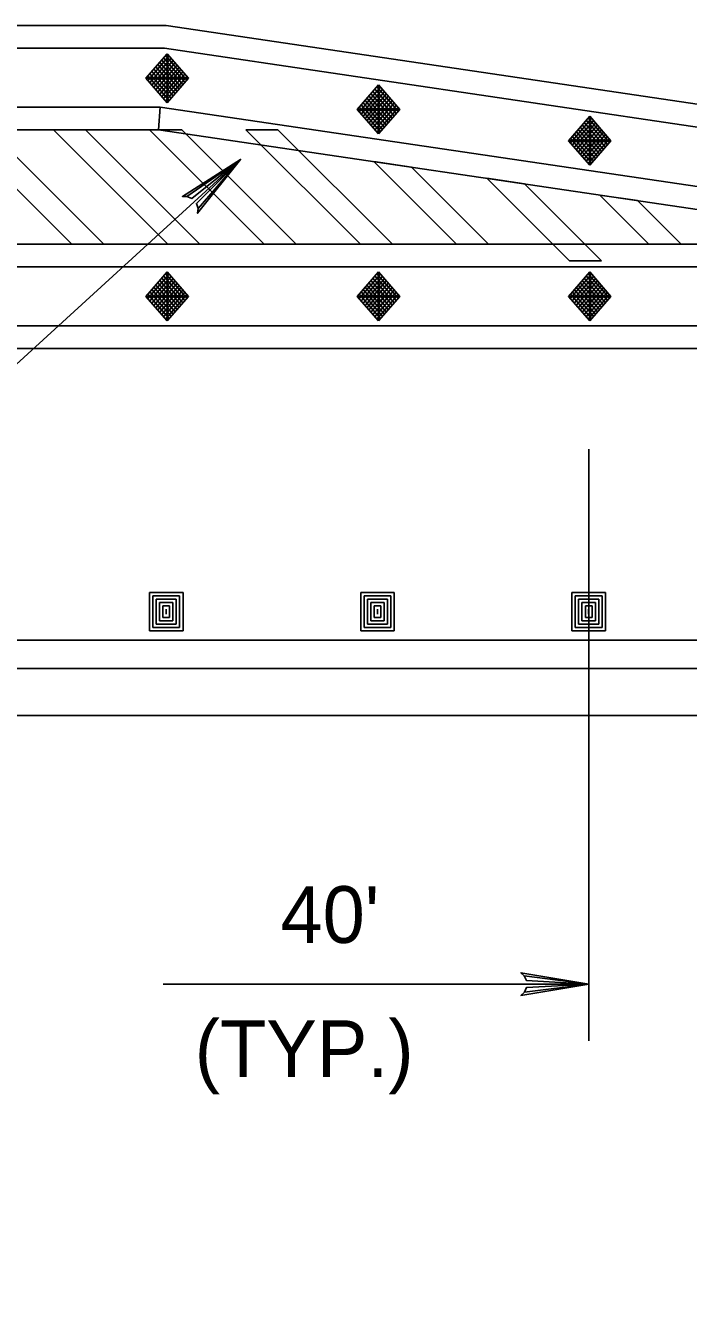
# Model space of a CAD drawing. Extents: x 639362 to 641108, y 298458 to 299646.
# Drawn here: x 639712.3 to 639747.4, y 298704.6 to 298772.2 of the extents above; entities that cross this region are included whole.
import ezdxf

# ---------------------------------------------------------------- set-up
doc = ezdxf.new("R2010")
doc.units = 0
doc.layers.add('2', color=7, linetype='Continuous')
doc.layers.add('3', color=7, linetype='Continuous')

# ---------------------------------------------------------------- blocks, each defined once
blk = doc.blocks.new('RARROW')
at = {"layer": '3'}
blk.add_lwpolyline([(-2.2695, 0.285), (-2.184875, 0.12075), (0, 0), (-2.2695, 0.285), (-2.38575, 0.384625), (0, 0), (-2.183125, -0.108), (-2.262875, -0.2705), (0, 0), (-2.38575, -0.379125), (-2.262875, -0.2705)], dxfattribs=at)

msp = doc.modelspace()

# ---------------------------------------------------------------- linework, layer by layer
at = {"layer": '2'}
for p, q in [((639719.726, 298772.157), (639431.255, 298772.157)), ((639797.996, 298760.59), (639719.726, 298772.157)), ((639431.255, 298770.957), (639719.637, 298770.957)), ((639719.779, 298770.666), (639718.652, 298769.371)), ((639719.884, 298770.547), (639718.77, 298769.268)), ((639719.637, 298770.957), (639797.908, 298759.39)), ((639719.696, 298770.57), (639720.823, 298769.275)), ((639720.907, 298769.371), (639719.779, 298770.666)), ((639719.779, 298770.666), (639719.779, 298768.076)), ((639719.988, 298770.427), (639718.86, 298769.131)), ((639720.092, 298770.307), (639718.965, 298769.011)), ((639720.197, 298770.187), (639719.069, 298768.891)), ((639719.069, 298769.851), (639720.197, 298768.555)), ((639720.301, 298770.067), (639719.174, 298768.771)), ((639719.174, 298769.971), (639720.301, 298768.675)), ((639719.278, 298770.091), (639720.406, 298768.795)), ((639720.406, 298769.947), (639719.278, 298768.651)), ((639719.382, 298770.211), (639720.51, 298768.915)), ((639720.51, 298769.827), (639719.382, 298768.531)), ((639719.487, 298770.331), (639720.614, 298769.035)), ((639719.591, 298770.451), (639720.719, 298769.155)), ((639718.652, 298769.371), (639719.779, 298768.076)), ((639718.652, 298769.371), (639720.907, 298769.371)), ((639718.756, 298769.491), (639719.884, 298768.196)), ((639718.86, 298769.611), (639719.988, 298768.315)), ((639718.965, 298769.731), (639720.092, 298768.435)), ((639720.614, 298769.707), (639719.487, 298768.411)), ((639720.719, 298769.587), (639719.591, 298768.292)), ((639720.823, 298769.467), (639719.696, 298768.172)), ((639719.779, 298768.076), (639720.907, 298769.371)), ((639730.963, 298769.014), (639729.835, 298767.718)), ((639731.067, 298768.894), (639729.954, 298767.615)), ((639731.172, 298768.774), (639730.044, 298767.478)), ((639731.276, 298768.654), (639730.149, 298767.359)), ((639731.381, 298768.534), (639730.253, 298767.239)), ((639730.462, 298768.438), (639731.589, 298767.143)), ((639730.566, 298768.558), (639731.694, 298767.263)), ((639730.671, 298768.678), (639731.798, 298767.383)), ((639730.775, 298768.798), (639731.903, 298767.502)), ((639730.879, 298768.918), (639732.007, 298767.622)), ((639732.091, 298767.718), (639730.963, 298769.014)), ((639730.963, 298769.014), (639730.963, 298766.423)), ((639719.409, 298767.845), (639606.893, 298767.845)), ((639719.409, 298767.845), (639719.32, 298766.645)), ((639719.32, 298766.645), (639719.409, 298767.845)), ((639776.623, 298759.39), (639719.409, 298767.845)), ((639729.94, 298767.838), (639731.067, 298766.543)), ((639730.044, 298767.958), (639731.172, 298766.663)), ((639730.149, 298768.078), (639731.276, 298766.783)), ((639730.253, 298768.198), (639731.381, 298766.903)), ((639731.485, 298768.414), (639730.357, 298767.119)), ((639730.357, 298768.318), (639731.485, 298767.023)), ((639731.589, 298768.294), (639730.462, 298766.999)), ((639731.694, 298768.174), (639730.566, 298766.879)), ((639731.798, 298768.054), (639730.671, 298766.759)), ((639731.903, 298767.934), (639730.775, 298766.639)), ((639732.007, 298767.814), (639730.879, 298766.519)), ((639729.835, 298767.718), (639730.963, 298766.423)), ((639729.835, 298767.718), (639732.091, 298767.718)), ((639730.963, 298766.423), (639732.091, 298767.718)), ((639742.147, 298767.361), (639741.019, 298766.066)), ((639742.251, 298767.241), (639741.138, 298765.962)), ((639742.356, 298767.121), (639741.228, 298765.826)), ((639741.959, 298767.145), (639743.086, 298765.85)), ((639742.063, 298767.265), (639743.191, 298765.97)), ((639743.274, 298766.066), (639742.147, 298767.361)), ((639742.147, 298767.361), (639742.147, 298764.77)), ((639623.223, 298766.645), (639719.32, 298766.645)), ((639714.724, 298760.59), (639708.664, 298766.645)), ((639710.362, 298766.645), (639716.422, 298760.59)), ((639719.818, 298760.59), (639713.757, 298766.645)), ((639713.757, 298766.645), (639715.455, 298766.645)), ((639715.455, 298766.645), (639721.515, 298760.59)), ((639724.911, 298760.59), (639718.851, 298766.645)), ((639718.851, 298766.645), (639720.549, 298766.645)), ((639719.32, 298766.645), (639760.294, 298760.59)), ((639720.549, 298766.645), (639726.609, 298760.59)), ((639730.005, 298760.59), (639723.944, 298766.645)), ((639723.944, 298766.645), (639725.642, 298766.645)), ((639725.642, 298766.645), (639731.702, 298760.59)), ((639742.46, 298767.001), (639741.332, 298765.706)), ((639741.332, 298766.426), (639742.46, 298765.13)), ((639742.564, 298766.881), (639741.437, 298765.586)), ((639741.437, 298766.545), (639742.564, 298765.25)), ((639742.669, 298766.761), (639741.541, 298765.466)), ((639741.541, 298766.665), (639742.669, 298765.37)), ((639741.646, 298766.785), (639742.773, 298765.49)), ((639742.773, 298766.641), (639741.646, 298765.346)), ((639741.75, 298766.905), (639742.878, 298765.61)), ((639742.878, 298766.522), (639741.75, 298765.226)), ((639741.854, 298767.025), (639742.982, 298765.73)), ((639741.019, 298766.066), (639742.147, 298764.77)), ((639741.019, 298766.066), (639743.274, 298766.066)), ((639741.124, 298766.186), (639742.251, 298764.89)), ((639741.228, 298766.306), (639742.356, 298765.01)), ((639742.982, 298766.402), (639741.854, 298765.106)), ((639743.086, 298766.282), (639741.959, 298764.986)), ((639743.191, 298766.162), (639742.063, 298764.866)), ((639742.147, 298764.77), (639743.274, 298766.066)), ((639657.3, 298704.573), (639723.666, 298765.08)), ((639730.724, 298764.96), (639735.098, 298760.59)), ((639732.717, 298764.666), (639730.724, 298764.96)), ((639736.796, 298760.59), (639732.717, 298764.666)), ((639736.702, 298764.077), (639741.076, 298759.707)), ((639738.695, 298763.782), (639736.702, 298764.077)), ((639742.774, 298759.707), (639738.695, 298763.782)), ((639745.285, 298760.59), (639742.68, 298763.193)), ((639742.68, 298763.193), (639744.672, 298762.899)), ((639744.672, 298762.899), (639746.983, 298760.59)), ((639760.294, 298760.59), (639664.196, 298760.59)), ((639716.422, 298760.59), (639714.724, 298760.59)), ((639721.515, 298760.59), (639719.818, 298760.59)), ((639726.609, 298760.59), (639724.911, 298760.59)), ((639731.702, 298760.59), (639730.005, 298760.59)), ((639735.098, 298760.59), (639736.796, 298760.59)), ((639746.983, 298760.59), (639745.285, 298760.59)), ((639741.076, 298759.707), (639742.774, 298759.707)), ((639664.108, 298759.39), (639776.623, 298759.39)), ((639719.779, 298759.13), (639718.652, 298757.835)), ((639719.884, 298759.01), (639718.77, 298757.731)), ((639719.696, 298759.034), (639720.823, 298757.739)), ((639720.907, 298757.835), (639719.779, 298759.13)), ((639719.779, 298759.13), (639719.779, 298756.539)), ((639730.963, 298759.13), (639729.835, 298757.835)), ((639731.067, 298759.01), (639729.954, 298757.731)), ((639730.879, 298759.034), (639732.007, 298757.739)), ((639732.091, 298757.835), (639730.963, 298759.13)), ((639730.963, 298759.13), (639730.963, 298756.539)), ((639742.147, 298759.13), (639741.019, 298757.835)), ((639742.251, 298759.01), (639741.138, 298757.731)), ((639742.063, 298759.034), (639743.191, 298757.739)), ((639743.274, 298757.835), (639742.147, 298759.13)), ((639742.147, 298759.13), (639742.147, 298756.539)), ((639719.988, 298758.89), (639718.86, 298757.595)), ((639720.092, 298758.77), (639718.965, 298757.475)), ((639720.197, 298758.65), (639719.069, 298757.355)), ((639719.069, 298758.314), (639720.197, 298757.019)), ((639720.301, 298758.53), (639719.174, 298757.235)), ((639719.174, 298758.434), (639720.301, 298757.139)), ((639719.278, 298758.554), (639720.406, 298757.259)), ((639720.406, 298758.41), (639719.278, 298757.115)), ((639719.382, 298758.674), (639720.51, 298757.379)), ((639719.487, 298758.794), (639720.614, 298757.499)), ((639719.591, 298758.914), (639720.719, 298757.619)), ((639731.172, 298758.89), (639730.044, 298757.595)), ((639731.276, 298758.77), (639730.149, 298757.475)), ((639731.381, 298758.65), (639730.253, 298757.355)), ((639730.253, 298758.314), (639731.381, 298757.019)), ((639731.485, 298758.53), (639730.357, 298757.235)), ((639730.357, 298758.434), (639731.485, 298757.139)), ((639730.462, 298758.554), (639731.589, 298757.259)), ((639731.589, 298758.41), (639730.462, 298757.115)), ((639730.566, 298758.674), (639731.694, 298757.379)), ((639730.671, 298758.794), (639731.798, 298757.499)), ((639730.775, 298758.914), (639731.903, 298757.619)), ((639742.356, 298758.89), (639741.228, 298757.595)), ((639742.46, 298758.77), (639741.332, 298757.475)), ((639742.564, 298758.65), (639741.437, 298757.355)), ((639741.437, 298758.314), (639742.564, 298757.019)), ((639742.669, 298758.53), (639741.541, 298757.235)), ((639741.541, 298758.434), (639742.669, 298757.139)), ((639741.646, 298758.554), (639742.773, 298757.259)), ((639742.773, 298758.41), (639741.646, 298757.115)), ((639741.75, 298758.674), (639742.878, 298757.379)), ((639741.854, 298758.794), (639742.982, 298757.499)), ((639741.959, 298758.914), (639743.086, 298757.619)), ((639718.652, 298757.835), (639719.779, 298756.539)), ((639718.652, 298757.835), (639720.907, 298757.835)), ((639718.756, 298757.955), (639719.884, 298756.659)), ((639718.86, 298758.075), (639719.988, 298756.779)), ((639718.965, 298758.194), (639720.092, 298756.899)), ((639720.51, 298758.29), (639719.382, 298756.995)), ((639720.614, 298758.17), (639719.487, 298756.875)), ((639720.719, 298758.051), (639719.591, 298756.755)), ((639720.823, 298757.931), (639719.696, 298756.635)), ((639719.779, 298756.539), (639720.907, 298757.835)), ((639729.835, 298757.835), (639730.963, 298756.539)), ((639729.835, 298757.835), (639732.091, 298757.835)), ((639729.94, 298757.955), (639731.067, 298756.659)), ((639730.044, 298758.075), (639731.172, 298756.779)), ((639730.149, 298758.194), (639731.276, 298756.899)), ((639731.694, 298758.29), (639730.566, 298756.995)), ((639731.798, 298758.17), (639730.671, 298756.875)), ((639731.903, 298758.051), (639730.775, 298756.755)), ((639732.007, 298757.931), (639730.879, 298756.635)), ((639730.963, 298756.539), (639732.091, 298757.835)), ((639741.019, 298757.835), (639742.147, 298756.539)), ((639741.019, 298757.835), (639743.274, 298757.835)), ((639741.124, 298757.955), (639742.251, 298756.659)), ((639741.228, 298758.075), (639742.356, 298756.779)), ((639741.332, 298758.194), (639742.46, 298756.899)), ((639742.878, 298758.29), (639741.75, 298756.995)), ((639742.982, 298758.17), (639741.854, 298756.875)), ((639743.086, 298758.051), (639741.959, 298756.755)), ((639743.191, 298757.931), (639742.063, 298756.635)), ((639742.147, 298756.539), (639743.274, 298757.835)), ((639663.879, 298756.279), (639952.262, 298756.279)), ((639952.262, 298755.079), (639663.791, 298755.079)), ((639742.105, 298749.761), (639742.105, 298718.456)), ((639718.841, 298742.179), (639720.616, 298742.179)), ((639718.841, 298740.14), (639718.841, 298742.179)), ((639720.616, 298742.179), (639720.616, 298740.14)), ((639730.024, 298742.179), (639731.799, 298742.179)), ((639730.024, 298740.14), (639730.024, 298742.179)), ((639731.799, 298742.179), (639731.799, 298740.14)), ((639741.208, 298742.179), (639742.983, 298742.179)), ((639741.208, 298740.14), (639741.208, 298742.179)), ((639742.983, 298742.179), (639742.983, 298740.14)), ((639719.018, 298742.001), (639720.437, 298742.001)), ((639719.018, 298740.317), (639719.018, 298742.001)), ((639719.196, 298741.824), (639720.26, 298741.824)), ((639719.196, 298740.495), (639719.196, 298741.824)), ((639719.373, 298740.672), (639719.373, 298741.647)), ((639719.373, 298741.647), (639720.082, 298741.647)), ((639719.551, 298741.471), (639719.905, 298741.471)), ((639719.551, 298740.849), (639719.551, 298741.471)), ((639719.905, 298741.471), (639719.905, 298740.849)), ((639720.082, 298741.647), (639720.082, 298740.672)), ((639720.26, 298741.824), (639720.26, 298740.495)), ((639720.437, 298742.001), (639720.437, 298740.317)), ((639730.201, 298742.001), (639731.621, 298742.001)), ((639730.201, 298740.317), (639730.201, 298742.001)), ((639730.38, 298741.824), (639731.444, 298741.824)), ((639730.38, 298740.495), (639730.38, 298741.824)), ((639730.557, 298740.672), (639730.557, 298741.647)), ((639730.557, 298741.647), (639731.266, 298741.647)), ((639730.735, 298741.471), (639731.089, 298741.471)), ((639730.735, 298740.849), (639730.735, 298741.471)), ((639731.089, 298741.471), (639731.089, 298740.849)), ((639731.266, 298741.647), (639731.266, 298740.672)), ((639731.444, 298741.824), (639731.444, 298740.495)), ((639731.621, 298742.001), (639731.621, 298740.317)), ((639741.385, 298742.001), (639742.805, 298742.001)), ((639741.385, 298740.317), (639741.385, 298742.001)), ((639741.564, 298741.824), (639742.628, 298741.824)), ((639741.564, 298740.495), (639741.564, 298741.824)), ((639741.74, 298740.672), (639741.74, 298741.647)), ((639741.74, 298741.647), (639742.45, 298741.647)), ((639741.919, 298741.471), (639742.273, 298741.471)), ((639741.919, 298740.849), (639741.919, 298741.471)), ((639742.273, 298741.471), (639742.273, 298740.849)), ((639742.45, 298741.647), (639742.45, 298740.672)), ((639742.628, 298741.824), (639742.628, 298740.495)), ((639742.805, 298742.001), (639742.805, 298740.317)), ((639719.905, 298740.849), (639719.551, 298740.849)), ((639719.726, 298741.294), (639719.726, 298741.026)), ((639731.089, 298740.849), (639730.735, 298740.849)), ((639730.909, 298741.294), (639730.909, 298741.026)), ((639742.273, 298740.849), (639741.919, 298740.849)), ((639742.093, 298741.294), (639742.093, 298741.026)), ((639720.616, 298740.14), (639718.841, 298740.14)), ((639720.437, 298740.317), (639719.018, 298740.317)), ((639720.26, 298740.495), (639719.196, 298740.495)), ((639720.082, 298740.672), (639719.373, 298740.672)), ((639731.799, 298740.14), (639730.024, 298740.14)), ((639731.621, 298740.317), (639730.201, 298740.317)), ((639731.444, 298740.495), (639730.38, 298740.495)), ((639731.266, 298740.672), (639730.557, 298740.672)), ((639742.983, 298740.14), (639741.208, 298740.14)), ((639742.805, 298740.317), (639741.385, 298740.317)), ((639742.628, 298740.495), (639741.564, 298740.495)), ((639742.45, 298740.672), (639741.74, 298740.672)), ((639431.348, 298739.66), (639952.736, 298739.66)), ((639431.348, 298738.16), (639952.736, 298738.16)), ((639431.348, 298735.66), (639952.736, 298735.66)), ((639719.572, 298721.456), (639742.105, 298721.456))]:
    msp.add_line(p, q, dxfattribs=at)

# ---------------------------------------------------------------- block references
at = {"layer": '2', "xscale": 1.5089217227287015, "yscale": 1.5711553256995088, "rotation": 41.96912032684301}
msp.add_blockref('RARROW', (639723.666, 298765.08), dxfattribs=at)
at = {"layer": '2', "xscale": 1.5089217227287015, "yscale": 1.5711553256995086}
msp.add_blockref('RARROW', (639742.105, 298721.456), dxfattribs=at)

# ---------------------------------------------------------------- texts
at = {"layer": '2'}
for s, p in [("40'", (639725.78, 298723.64)), ('(TYP.)', (639721.238, 298716.544))]:
    msp.add_text(s, height=3, dxfattribs=at).set_placement(p)

doc.saveas('drawing.dxf')
